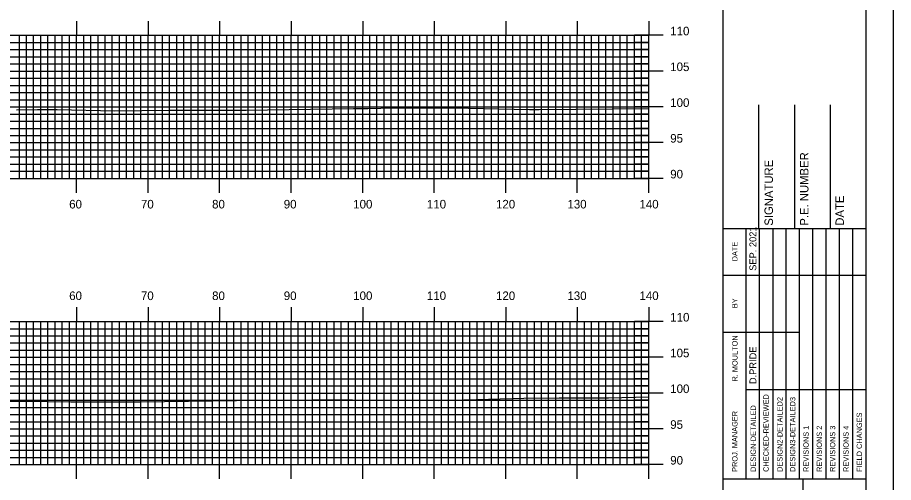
# Model space of a CAD drawing. Extents: x 1778712 to 1779055, y 442591 to 442811.
# Drawn here: x 1778929.6 to 1779052, y 442686.2 to 442751.2 of the extents above; entities that cross this region are included whole.
import ezdxf

# ---------------------------------------------------------------- set-up
doc = ezdxf.new("R2010")
doc.units = 0
for name, color, linetype in [('BORDER', 7, 'Continuous'), ('H_V ANNOTATION', 7, 'Continuous'), ('MAJOR', 7, 'Continuous'), ('MINOR', 7, 'Continuous'), ('PLOT BOUNDARY', 7, 'Continuous'), ('S_Roadway_Centerline', 7, 'Continuous')]:
    doc.layers.add(name, color=color, linetype=linetype)

msp = doc.modelspace()

# ---------------------------------------------------------------- linework, layer by layer
at = {"layer": 'BORDER'}
for p, q in [((1779028.22, 442596.67), (1779028.22, 442806.67)), ((1779033.22, 442721.67), (1779033.22, 442738.97)), ((1779038.22, 442721.67), (1779038.22, 442738.97)), ((1779043.22, 442721.67), (1779043.22, 442738.97)), ((1779028.22, 442721.67), (1779048.22, 442721.67)), ((1779028.22, 442686.67), (1779048.22, 442686.67)), ((1779039.4, 442616.67), (1779039.4, 442686.67))]:
    msp.add_line(p, q, dxfattribs=at)
msp.add_lwpolyline([(1778728.22, 442596.67), (1779048.22, 442596.67), (1779048.22, 442806.67), (1778728.22, 442806.67)], close=True, dxfattribs=at)
for points in [[(1779031.45, 442715.17), (1779031.45, 442721.67)], [(1779033.31, 442686.68), (1779033.31, 442721.67)], [(1779035.17, 442721.67), (1779035.17, 442686.68)], [(1779037.04, 442686.68), (1779037.04, 442721.67)], [(1779038.9, 442686.68), (1779038.9, 442721.67)], [(1779040.76, 442686.68), (1779040.76, 442721.67)], [(1779042.63, 442686.68), (1779042.63, 442721.67)], [(1779044.49, 442686.68), (1779044.49, 442721.67)], [(1779046.35, 442686.68), (1779046.35, 442721.67)], [(1779031.45, 442686.68), (1779031.45, 442720.26)], [(1779028.22, 442715.17), (1779048.22, 442715.17)], [(1779028.22, 442707.17), (1779031.45, 442707.17)], [(1779031.45, 442707.17), (1779038.9, 442707.17)], [(1779031.45, 442699.17), (1779048.22, 442699.17)]]:
    msp.add_lwpolyline(points, dxfattribs=at)
at = {"layer": 'MAJOR'}
for p, q in [((1778937.82, 442750.67), (1778937.82, 442748.67)), ((1778947.82, 442750.67), (1778947.82, 442748.67)), ((1778957.82, 442750.67), (1778957.82, 442748.67)), ((1778967.82, 442750.67), (1778967.82, 442748.67)), ((1778977.82, 442750.67), (1778977.82, 442748.67)), ((1778987.82, 442750.67), (1778987.82, 442748.67)), ((1778997.82, 442750.67), (1778997.82, 442748.67)), ((1779007.82, 442750.67), (1779007.82, 442748.67)), ((1779017.82, 442750.67), (1779017.82, 442748.67)), ((1778737.82, 442748.67), (1779017.82, 442748.67)), ((1778737.82, 442748.67), (1779017.82, 442748.67)), ((1778937.82, 442728.67), (1778937.82, 442748.67)), ((1778947.82, 442728.67), (1778947.82, 442748.67)), ((1778957.82, 442728.67), (1778957.82, 442748.67)), ((1778967.82, 442728.67), (1778967.82, 442748.67)), ((1778977.82, 442728.67), (1778977.82, 442748.67)), ((1778987.82, 442728.67), (1778987.82, 442748.67)), ((1778997.82, 442728.67), (1778997.82, 442748.67)), ((1779007.82, 442728.67), (1779007.82, 442748.67)), ((1779019.82, 442748.67), (1779015.81, 442748.67)), ((1779017.82, 442728.67), (1779017.82, 442748.67)), ((1779017.82, 442728.67), (1779017.82, 442748.67)), ((1778737.82, 442743.67), (1779017.82, 442743.67)), ((1779019.82, 442743.67), (1779015.81, 442743.67)), ((1778737.82, 442738.67), (1779017.82, 442738.67)), ((1779019.82, 442738.67), (1779015.81, 442738.67)), ((1778737.82, 442733.67), (1779017.82, 442733.67)), ((1779019.82, 442733.67), (1779015.81, 442733.67)), ((1778737.82, 442728.67), (1779017.82, 442728.67)), ((1778737.82, 442728.67), (1779017.82, 442728.67)), ((1778937.82, 442726.66), (1778937.82, 442728.67)), ((1778947.82, 442726.66), (1778947.82, 442728.67)), ((1778957.82, 442726.66), (1778957.82, 442728.67)), ((1778967.82, 442726.66), (1778967.82, 442728.67)), ((1778977.82, 442726.66), (1778977.82, 442728.67)), ((1778987.82, 442726.66), (1778987.82, 442728.67)), ((1778997.82, 442726.66), (1778997.82, 442728.67)), ((1779007.82, 442726.66), (1779007.82, 442728.67)), ((1779019.82, 442728.67), (1779015.81, 442728.67)), ((1779017.82, 442726.66), (1779017.82, 442728.67)), ((1778937.82, 442710.67), (1778937.82, 442708.67)), ((1778947.82, 442710.67), (1778947.82, 442708.67)), ((1778957.82, 442710.67), (1778957.82, 442708.67)), ((1778967.82, 442710.67), (1778967.82, 442708.67)), ((1778977.82, 442710.67), (1778977.82, 442708.67)), ((1778987.82, 442710.67), (1778987.82, 442708.67)), ((1778997.82, 442710.67), (1778997.82, 442708.67)), ((1779007.82, 442710.67), (1779007.82, 442708.67)), ((1779017.82, 442710.67), (1779017.82, 442708.67)), ((1778737.82, 442708.67), (1779017.82, 442708.67)), ((1778737.82, 442708.67), (1779017.82, 442708.67)), ((1778937.82, 442688.67), (1778937.82, 442708.67)), ((1778947.82, 442688.67), (1778947.82, 442708.67)), ((1778957.82, 442688.67), (1778957.82, 442708.67)), ((1778967.82, 442688.67), (1778967.82, 442708.67)), ((1778977.82, 442688.67), (1778977.82, 442708.67)), ((1778987.82, 442688.67), (1778987.82, 442708.67)), ((1778997.82, 442688.67), (1778997.82, 442708.67)), ((1779007.82, 442688.67), (1779007.82, 442708.67)), ((1779019.82, 442708.67), (1779015.81, 442708.67)), ((1779017.82, 442688.67), (1779017.82, 442708.67)), ((1779017.82, 442688.67), (1779017.82, 442708.67)), ((1778737.82, 442703.67), (1779017.82, 442703.67)), ((1779019.82, 442703.67), (1779015.81, 442703.67)), ((1778737.82, 442698.67), (1779017.82, 442698.67)), ((1779019.82, 442698.67), (1779015.81, 442698.67)), ((1778737.82, 442693.67), (1779017.82, 442693.67)), ((1779019.82, 442693.67), (1779015.81, 442693.67)), ((1778737.82, 442688.67), (1779017.82, 442688.67)), ((1778737.82, 442688.67), (1779017.82, 442688.67)), ((1778937.82, 442686.66), (1778937.82, 442688.67)), ((1778947.82, 442686.66), (1778947.82, 442688.67)), ((1778957.82, 442686.66), (1778957.82, 442688.67)), ((1778967.82, 442686.66), (1778967.82, 442688.67)), ((1778977.82, 442686.66), (1778977.82, 442688.67)), ((1778987.82, 442686.66), (1778987.82, 442688.67)), ((1778997.82, 442686.66), (1778997.82, 442688.67)), ((1779007.82, 442686.66), (1779007.82, 442688.67)), ((1779019.82, 442688.67), (1779015.81, 442688.67)), ((1779017.82, 442686.66), (1779017.82, 442688.67))]:
    msp.add_line(p, q, dxfattribs=at)
at = {"layer": 'MINOR'}
for p, q in [((1778929.82, 442728.67), (1778929.82, 442748.67)), ((1778930.82, 442728.67), (1778930.82, 442748.67)), ((1778931.82, 442728.67), (1778931.82, 442748.67)), ((1778932.82, 442728.67), (1778932.82, 442748.67)), ((1778933.82, 442728.67), (1778933.82, 442748.67)), ((1778934.82, 442728.67), (1778934.82, 442748.67)), ((1778935.82, 442728.67), (1778935.82, 442748.67)), ((1778936.82, 442728.67), (1778936.82, 442748.67)), ((1778938.82, 442728.67), (1778938.82, 442748.67)), ((1778939.82, 442728.67), (1778939.82, 442748.67)), ((1778940.82, 442728.67), (1778940.82, 442748.67)), ((1778941.82, 442728.67), (1778941.82, 442748.67)), ((1778942.82, 442728.67), (1778942.82, 442748.67)), ((1778943.82, 442728.67), (1778943.82, 442748.67)), ((1778944.82, 442728.67), (1778944.82, 442748.67)), ((1778945.82, 442728.67), (1778945.82, 442748.67)), ((1778946.82, 442728.67), (1778946.82, 442748.67)), ((1778948.82, 442728.67), (1778948.82, 442748.67)), ((1778949.82, 442728.67), (1778949.82, 442748.67)), ((1778950.82, 442728.67), (1778950.82, 442748.67)), ((1778951.82, 442728.67), (1778951.82, 442748.67)), ((1778952.82, 442728.67), (1778952.82, 442748.67)), ((1778953.82, 442728.67), (1778953.82, 442748.67)), ((1778954.82, 442728.67), (1778954.82, 442748.67)), ((1778955.82, 442728.67), (1778955.82, 442748.67)), ((1778956.82, 442728.67), (1778956.82, 442748.67)), ((1778958.82, 442728.67), (1778958.82, 442748.67)), ((1778959.82, 442728.67), (1778959.82, 442748.67)), ((1778960.82, 442728.67), (1778960.82, 442748.67)), ((1778961.82, 442728.67), (1778961.82, 442748.67)), ((1778962.82, 442728.67), (1778962.82, 442748.67)), ((1778963.82, 442728.67), (1778963.82, 442748.67)), ((1778964.82, 442728.67), (1778964.82, 442748.67)), ((1778965.82, 442728.67), (1778965.82, 442748.67)), ((1778966.82, 442728.67), (1778966.82, 442748.67)), ((1778968.82, 442728.67), (1778968.82, 442748.67)), ((1778969.82, 442728.67), (1778969.82, 442748.67)), ((1778970.82, 442728.67), (1778970.82, 442748.67)), ((1778971.82, 442728.67), (1778971.82, 442748.67)), ((1778972.82, 442728.67), (1778972.82, 442748.67)), ((1778973.82, 442728.67), (1778973.82, 442748.67)), ((1778974.82, 442728.67), (1778974.82, 442748.67)), ((1778975.82, 442728.67), (1778975.82, 442748.67)), ((1778976.82, 442728.67), (1778976.82, 442748.67)), ((1778978.82, 442728.67), (1778978.82, 442748.67)), ((1778979.82, 442728.67), (1778979.82, 442748.67)), ((1778980.82, 442728.67), (1778980.82, 442748.67)), ((1778981.82, 442728.67), (1778981.82, 442748.67)), ((1778982.82, 442728.67), (1778982.82, 442748.67)), ((1778983.82, 442728.67), (1778983.82, 442748.67)), ((1778984.82, 442728.67), (1778984.82, 442748.67)), ((1778985.82, 442728.67), (1778985.82, 442748.67)), ((1778986.82, 442728.67), (1778986.82, 442748.67)), ((1778988.82, 442728.67), (1778988.82, 442748.67)), ((1778989.82, 442728.67), (1778989.82, 442748.67)), ((1778990.82, 442728.67), (1778990.82, 442748.67)), ((1778991.82, 442728.67), (1778991.82, 442748.67)), ((1778992.82, 442728.67), (1778992.82, 442748.67)), ((1778993.82, 442728.67), (1778993.82, 442748.67)), ((1778994.82, 442728.67), (1778994.82, 442748.67)), ((1778995.82, 442728.67), (1778995.82, 442748.67)), ((1778996.82, 442728.67), (1778996.82, 442748.67)), ((1778998.82, 442728.67), (1778998.82, 442748.67)), ((1778999.82, 442728.67), (1778999.82, 442748.67)), ((1779000.82, 442728.67), (1779000.82, 442748.67)), ((1779001.82, 442728.67), (1779001.82, 442748.67)), ((1779002.82, 442728.67), (1779002.82, 442748.67)), ((1779003.82, 442728.67), (1779003.82, 442748.67)), ((1779004.82, 442728.67), (1779004.82, 442748.67)), ((1779005.82, 442728.67), (1779005.82, 442748.67)), ((1779006.82, 442728.67), (1779006.82, 442748.67)), ((1779008.82, 442728.67), (1779008.82, 442748.67)), ((1779009.82, 442728.67), (1779009.82, 442748.67)), ((1779010.82, 442728.67), (1779010.82, 442748.67)), ((1779011.82, 442728.67), (1779011.82, 442748.67)), ((1779012.82, 442728.67), (1779012.82, 442748.67)), ((1779013.82, 442728.67), (1779013.82, 442748.67)), ((1779014.82, 442728.67), (1779014.82, 442748.67)), ((1779015.82, 442728.67), (1779015.82, 442748.67)), ((1779016.82, 442728.67), (1779016.82, 442748.67)), ((1778737.82, 442747.67), (1779017.82, 442747.67)), ((1779017.82, 442747.67), (1779015.81, 442747.67)), ((1778737.82, 442746.67), (1779017.82, 442746.67)), ((1779017.82, 442746.67), (1779015.81, 442746.67)), ((1778737.82, 442745.67), (1779017.82, 442745.67)), ((1779017.82, 442745.67), (1779015.81, 442745.67)), ((1778737.82, 442744.67), (1779017.82, 442744.67)), ((1779017.82, 442744.67), (1779015.81, 442744.67)), ((1778737.82, 442742.67), (1779017.82, 442742.67)), ((1779017.82, 442742.67), (1779015.81, 442742.67)), ((1778737.82, 442741.67), (1779017.82, 442741.67)), ((1779017.82, 442741.67), (1779015.81, 442741.67)), ((1778737.82, 442740.67), (1779017.82, 442740.67)), ((1779017.82, 442740.67), (1779015.81, 442740.67)), ((1778737.82, 442739.67), (1779017.82, 442739.67)), ((1779017.82, 442739.67), (1779015.81, 442739.67)), ((1778737.82, 442737.67), (1779017.82, 442737.67)), ((1779017.82, 442737.67), (1779015.81, 442737.67)), ((1778737.82, 442736.67), (1779017.82, 442736.67)), ((1779017.82, 442736.67), (1779015.81, 442736.67)), ((1778737.82, 442735.67), (1779017.82, 442735.67)), ((1779017.82, 442735.67), (1779015.81, 442735.67)), ((1778737.82, 442734.67), (1779017.82, 442734.67)), ((1779017.82, 442734.67), (1779015.81, 442734.67)), ((1778737.82, 442732.67), (1779017.82, 442732.67)), ((1778737.82, 442731.67), (1779017.82, 442731.67)), ((1779017.82, 442732.67), (1779015.81, 442732.67)), ((1779017.82, 442731.67), (1779015.81, 442731.67)), ((1778737.82, 442730.67), (1779017.82, 442730.67)), ((1779017.82, 442730.67), (1779015.81, 442730.67)), ((1778737.82, 442729.67), (1779017.82, 442729.67)), ((1779017.82, 442729.67), (1779015.81, 442729.67)), ((1778929.82, 442688.67), (1778929.82, 442708.67)), ((1778930.82, 442688.67), (1778930.82, 442708.67)), ((1778931.82, 442688.67), (1778931.82, 442708.67)), ((1778932.82, 442688.67), (1778932.82, 442708.67)), ((1778933.82, 442688.67), (1778933.82, 442708.67)), ((1778934.82, 442688.67), (1778934.82, 442708.67)), ((1778935.82, 442688.67), (1778935.82, 442708.67)), ((1778936.82, 442688.67), (1778936.82, 442708.67)), ((1778938.82, 442688.67), (1778938.82, 442708.67)), ((1778939.82, 442688.67), (1778939.82, 442708.67)), ((1778940.82, 442688.67), (1778940.82, 442708.67)), ((1778941.82, 442688.67), (1778941.82, 442708.67)), ((1778942.82, 442688.67), (1778942.82, 442708.67)), ((1778943.82, 442688.67), (1778943.82, 442708.67)), ((1778944.82, 442688.67), (1778944.82, 442708.67)), ((1778945.82, 442688.67), (1778945.82, 442708.67)), ((1778946.82, 442688.67), (1778946.82, 442708.67)), ((1778948.82, 442688.67), (1778948.82, 442708.67)), ((1778949.82, 442688.67), (1778949.82, 442708.67)), ((1778950.82, 442688.67), (1778950.82, 442708.67)), ((1778951.82, 442688.67), (1778951.82, 442708.67)), ((1778952.82, 442688.67), (1778952.82, 442708.67)), ((1778953.82, 442688.67), (1778953.82, 442708.67)), ((1778954.82, 442688.67), (1778954.82, 442708.67)), ((1778955.82, 442688.67), (1778955.82, 442708.67)), ((1778956.82, 442688.67), (1778956.82, 442708.67)), ((1778958.82, 442688.67), (1778958.82, 442708.67)), ((1778959.82, 442688.67), (1778959.82, 442708.67)), ((1778960.82, 442688.67), (1778960.82, 442708.67)), ((1778961.82, 442688.67), (1778961.82, 442708.67)), ((1778962.82, 442688.67), (1778962.82, 442708.67)), ((1778963.82, 442688.67), (1778963.82, 442708.67)), ((1778964.82, 442688.67), (1778964.82, 442708.67)), ((1778965.82, 442688.67), (1778965.82, 442708.67)), ((1778966.82, 442688.67), (1778966.82, 442708.67)), ((1778968.82, 442688.67), (1778968.82, 442708.67)), ((1778969.82, 442688.67), (1778969.82, 442708.67)), ((1778970.82, 442688.67), (1778970.82, 442708.67)), ((1778971.82, 442688.67), (1778971.82, 442708.67)), ((1778972.82, 442688.67), (1778972.82, 442708.67)), ((1778973.82, 442688.67), (1778973.82, 442708.67)), ((1778974.82, 442688.67), (1778974.82, 442708.67)), ((1778975.82, 442688.67), (1778975.82, 442708.67)), ((1778976.82, 442688.67), (1778976.82, 442708.67)), ((1778978.82, 442688.67), (1778978.82, 442708.67)), ((1778979.82, 442688.67), (1778979.82, 442708.67)), ((1778980.82, 442688.67), (1778980.82, 442708.67)), ((1778981.82, 442688.67), (1778981.82, 442708.67)), ((1778982.82, 442688.67), (1778982.82, 442708.67)), ((1778983.82, 442688.67), (1778983.82, 442708.67)), ((1778984.82, 442688.67), (1778984.82, 442708.67)), ((1778985.82, 442688.67), (1778985.82, 442708.67)), ((1778986.82, 442688.67), (1778986.82, 442708.67)), ((1778988.82, 442688.67), (1778988.82, 442708.67)), ((1778989.82, 442688.67), (1778989.82, 442708.67)), ((1778990.82, 442688.67), (1778990.82, 442708.67)), ((1778991.82, 442688.67), (1778991.82, 442708.67)), ((1778992.82, 442688.67), (1778992.82, 442708.67)), ((1778993.82, 442688.67), (1778993.82, 442708.67)), ((1778994.82, 442688.67), (1778994.82, 442708.67)), ((1778995.82, 442688.67), (1778995.82, 442708.67)), ((1778996.82, 442688.67), (1778996.82, 442708.67)), ((1778998.82, 442688.67), (1778998.82, 442708.67)), ((1778999.82, 442688.67), (1778999.82, 442708.67)), ((1779000.82, 442688.67), (1779000.82, 442708.67)), ((1779001.82, 442688.67), (1779001.82, 442708.67)), ((1779002.82, 442688.67), (1779002.82, 442708.67)), ((1779003.82, 442688.67), (1779003.82, 442708.67)), ((1779004.82, 442688.67), (1779004.82, 442708.67)), ((1779005.82, 442688.67), (1779005.82, 442708.67)), ((1779006.82, 442688.67), (1779006.82, 442708.67)), ((1779008.82, 442688.67), (1779008.82, 442708.67)), ((1779009.82, 442688.67), (1779009.82, 442708.67)), ((1779010.82, 442688.67), (1779010.82, 442708.67)), ((1779011.82, 442688.67), (1779011.82, 442708.67)), ((1779012.82, 442688.67), (1779012.82, 442708.67)), ((1779013.82, 442688.67), (1779013.82, 442708.67)), ((1779014.82, 442688.67), (1779014.82, 442708.67)), ((1779015.82, 442688.67), (1779015.82, 442708.67)), ((1779016.82, 442688.67), (1779016.82, 442708.67)), ((1778737.82, 442707.67), (1779017.82, 442707.67)), ((1779017.82, 442707.67), (1779015.81, 442707.67)), ((1778737.82, 442706.67), (1779017.82, 442706.67)), ((1779017.82, 442706.67), (1779015.81, 442706.67)), ((1778737.82, 442705.67), (1779017.82, 442705.67)), ((1778737.82, 442704.67), (1779017.82, 442704.67)), ((1779017.82, 442705.67), (1779015.81, 442705.67)), ((1779017.82, 442704.67), (1779015.81, 442704.67)), ((1778737.82, 442702.67), (1779017.82, 442702.67)), ((1779017.82, 442702.67), (1779015.81, 442702.67)), ((1778737.82, 442701.67), (1779017.82, 442701.67)), ((1779017.82, 442701.67), (1779015.81, 442701.67)), ((1778737.82, 442700.67), (1779017.82, 442700.67)), ((1778737.82, 442699.67), (1779017.82, 442699.67)), ((1779017.82, 442700.67), (1779015.81, 442700.67)), ((1779017.82, 442699.67), (1779015.81, 442699.67)), ((1778737.82, 442697.67), (1779017.82, 442697.67)), ((1779017.82, 442697.67), (1779015.81, 442697.67)), ((1778737.82, 442696.67), (1779017.82, 442696.67)), ((1779017.82, 442696.67), (1779015.81, 442696.67)), ((1778737.82, 442695.67), (1779017.82, 442695.67)), ((1779017.82, 442695.67), (1779015.81, 442695.67)), ((1778737.82, 442694.67), (1779017.82, 442694.67)), ((1779017.82, 442694.67), (1779015.81, 442694.67)), ((1778737.82, 442692.67), (1779017.82, 442692.67)), ((1779017.82, 442692.67), (1779015.81, 442692.67)), ((1778737.82, 442691.67), (1779017.82, 442691.67)), ((1779017.82, 442691.67), (1779015.81, 442691.67)), ((1778737.82, 442690.67), (1779017.82, 442690.67)), ((1779017.82, 442690.67), (1779015.81, 442690.67)), ((1778737.82, 442689.67), (1779017.82, 442689.67)), ((1779017.82, 442689.67), (1779015.81, 442689.67))]:
    msp.add_line(p, q, dxfattribs=at)
at = {"layer": 'PLOT BOUNDARY'}
msp.add_lwpolyline([(1778712.03, 442590.55), (1779052.03, 442590.55), (1779052.03, 442810.55), (1778712.03, 442810.55)], close=True, dxfattribs=at)
at = {"layer": 'S_Roadway_Centerline'}
for points in [[(1778929.4, 442738.24), (1778932.36, 442738.29), (1778935.12, 442738.28), (1778943.15, 442738.12), (1778950.73, 442738.2), (1778961.51, 442738.22), (1778976.53, 442738.44), (1778978.52, 442738.46), (1778980.38, 442738.48), (1778990.48, 442738.53), (1779001.15, 442738.3), (1779002.51, 442738.29), (1779017.82, 442738.43)], [(1778923.55, 442697.44), (1778930.54, 442697.55), (1778937.01, 442697.45), (1778941.75, 442697.45), (1778946.78, 442697.45), (1778960.18, 442697.64), (1778970.83, 442697.73), (1778976.4, 442697.72), (1778981.48, 442697.67), (1778988.47, 442697.65), (1778995.41, 442697.8), (1779000.36, 442697.97), (1779005.31, 442698), (1779012.18, 442698.01), (1779017.82, 442698.12)]]:
    msp.add_lwpolyline(points, dxfattribs=at)

# ---------------------------------------------------------------- texts
at = {"layer": 'BORDER'}
for s, height, p in [('P.E. NUMBER', 1.1811, (1779040.14, 442722.06)), ('SIGNATURE', 1.181, (1779035.18, 442722.06)), ('DATE', 1.181, (1779045.1, 442722.06)), ('SEP. 2021', 0.969, (1779032.86, 442715.76)), ('DATE', 0.743, (1779030.22, 442717.08)), ('BY', 0.743, (1779030.22, 442710.54)), ('R. MOULTON', 0.745, (1779030.23, 442700.28)), ('D.PRIDE', 0.969, (1779032.86, 442699.92)), ('CHECKED-REVIEWED', 0.7455, (1779034.58, 442687.65)), ('DESIGN2-DETAILED2', 0.7455, (1779036.52, 442687.65)), ('DESIGN3-DETAILED3', 0.7455, (1779038.3, 442687.65)), ('DESIGN-DETAILED', 0.7455, (1779032.79, 442687.65)), ('PROJ. MANAGER', 0.7455, (1779030.22, 442687.65)), ('FIELD CHANGES', 0.7455, (1779047.62, 442687.65)), ('REVISIONS 1', 0.7455, (1779040.17, 442687.65)), ('REVISIONS 2', 0.7455, (1779042.03, 442687.65)), ('REVISIONS 3', 0.7455, (1779043.89, 442687.65)), ('REVISIONS 4', 0.7455, (1779045.76, 442687.65))]:
    msp.add_text(s, height=height, rotation=90, dxfattribs=at).set_placement(p)
at = {"layer": 'H_V ANNOTATION'}
for s, p in [('110', (1779020.82, 442748.67)), ('105', (1779020.82, 442743.67)), ('100', (1779020.82, 442738.67)), ('95', (1779020.82, 442733.67)), ('90', (1779020.82, 442728.67)), ('60', (1778936.79, 442724.47)), ('70', (1778946.82, 442724.47)), ('80', (1778956.77, 442724.47)), ('90', (1778966.79, 442724.47)), ('100', (1778976.5, 442724.47)), ('110', (1778986.8, 442724.47)), ('120', (1778996.46, 442724.47)), ('130', (1779006.45, 442724.47)), ('140', (1779016.52, 442724.47)), ('60', (1778936.79, 442711.67)), ('70', (1778946.82, 442711.67)), ('80', (1778956.77, 442711.67)), ('90', (1778966.79, 442711.67)), ('100', (1778976.5, 442711.67)), ('110', (1778986.8, 442711.67)), ('120', (1778996.46, 442711.67)), ('130', (1779006.45, 442711.67)), ('140', (1779016.52, 442711.67)), ('110', (1779020.82, 442708.67)), ('105', (1779020.82, 442703.67)), ('100', (1779020.82, 442698.67)), ('95', (1779020.82, 442693.67)), ('90', (1779020.82, 442688.67))]:
    msp.add_text(s, height=1.2, dxfattribs=at).set_placement(p)

doc.saveas('drawing.dxf')
